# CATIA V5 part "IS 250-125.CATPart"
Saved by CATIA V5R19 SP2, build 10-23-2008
Part number: IS 250-125
Bounding box of the stored display mesh (mm): x -18.951 to 18.951, y -18.952 to 18.952, z 0 to 300
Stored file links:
  C:\Users\Bora\Desktop\3D Katı model\IS serisi\IS 250\IS 250-125.CATPart
  C:\Program Files\Dassault Systemes\B19\intel_a\reffiles\standard\MetricThickPitch.txt
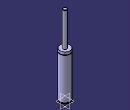
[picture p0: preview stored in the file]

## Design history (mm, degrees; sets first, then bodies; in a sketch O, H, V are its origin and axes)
Body1 (main body)
  Sketch1 on yz-plane, origin (0, 0, 0), H (0, 1, 0), V (0, 0, 1)
    point P3 (7.5, 299)
    point P5 (7.5, 299)
    point P7 (19, 163.5)
    point P8 (19, 161.5)
    point P12 (19, 161.5)
    point P13 (19, 163.5)
    line L1 (19, 0) -> (19, 4)
    line L2 (7.5, 299) -> (7.5, 173)
    arc A1 centre (6.5, 299) radius 1 from (7.5, 299) to (6.5, 300) ccw
    arc A2 centre (19, 162.5) radius 1 from (19, 163.5) to (19, 161.5) ccw
    line L3 (16.5, 7.5) -> (16.5, 4)
    line L4 (19, 7.5) -> (19, 161.5)
    line L5 (19, 163.5) -> (19, 173)
    line L6 (6.5, 300) -> (0, 300)
    point P15 (0, 300)
    line L7 (7.5, 173) -> (19, 173)
    line L8 (0, 0) -> (19, 0)
    line L9 (16.5, 7.5) -> (19, 7.5)
    line L10 (16.5, 4) -> (19, 4)
    coincidence: P15 V, P3 P5, P7 P13, P8 P12
    tangency: L6 A1
    horizontal: L7 H, L8 H, L9 H, L10 H
  Shaft1: profile Sketch1, axis Sketch1.V, angle 360
  Sketch2 on face of Shaft1 from Sketch1.L8, origin (0, 0, 0), H (1, 0, 0), V (0, -1, 0)
    point P1 (0, 0)
  Hole1: placed by Sketch2, at (0, 0, 0) direction (0, 0, 1), diameter 6.647, depth 7, threaded "M8", thread diameter 8, thread depth 7, pitch 1.25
